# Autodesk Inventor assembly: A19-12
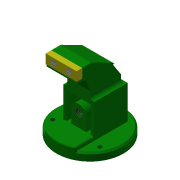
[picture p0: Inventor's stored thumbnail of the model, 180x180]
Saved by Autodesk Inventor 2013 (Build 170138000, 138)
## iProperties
Created: 2008-07
Part Number: A19-12
Document SubType Name: Assembly
Designer: y-shimohigashi
Stock Number: A19-12
Author: y-shimohigashi
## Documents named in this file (4)
- C:\Users\t-komatsu\Desktop\新しいフォルダー\Inventor2013基礎コース\練習問題-19\A19-12.iam
- C:\Users\t-komatsu\Desktop\新しいフォルダー\Inventor2013基礎コース\練習問題-19\P19-2ベース.ipt
- C:\Users\t-komatsu\Desktop\新しいフォルダー\Inventor2013基礎コース\練習問題-19\P19-4締付板.ipt
- C:\Users\t-komatsu\Desktop\新しいフォルダー\Inventor2013基礎コース\練習問題-19\P19-11ボルト.ipt
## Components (4 placed, 3 different names)
1. P19-2ベース:1
2. P19-4締付板:1 — 挿入:2, 挿入:3
3. P19-11ボルト:1 — 挿入:2
4. P19-11ボルト:2 — 挿入:3
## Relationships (2: Insert 2)
- 挿入:2 [Insert]: P19-4締付板:1 ↔ P19-11ボルト:1
- 挿入:3 [Insert]: P19-4締付板:1 ↔ P19-11ボルト:2
